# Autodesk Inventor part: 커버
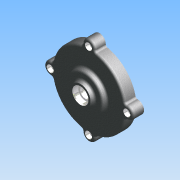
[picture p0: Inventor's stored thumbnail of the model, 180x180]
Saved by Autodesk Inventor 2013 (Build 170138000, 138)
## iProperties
Company: 한국ATC센터
Created: 2014-07
Part Number: 커버
Document SubType Name: 모델링
Designer: KYOUNG IL JANG
Material: 알루미늄 6061
Mass: 196.659 g
Surface Area: 278.607 cm^2
Volume: 72.5678 cm^3
Density: 2.71 g/cm^3
변환 표준: STEP AP214IS
파일 이름: C:\Users\SeoGD\Desktop\?쒗뿕\而ㅻ쾭-1.stp
전처리기: Build: 253, Release: 2010 SP1 - Date: Wed 07/29/2009
전송 단위: 밀리미터
불확실성: 0.01
Author: KYOUNG IL JANG
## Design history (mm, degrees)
sketch "스케치1"
  geometry: L1 (0, 0)-(0, 26); L2 (50, 0)-(50, 15); L3 (50, 15)-(25, 15); L4 (25, 15)-(25, 21); L5 (25, 21)-(15, 21); L6 (15, 21)-(13.66, 26); L7 (13.66, 26)-(10, 26); L8 (50, 0)-(45, 0); L9 (45, 0)-(45, 10); L10 (45, 10)-(14.5, 10); L11 (14.5, 10)-(13.266, 3); L12 (13.266, 3)-(11, 3); L13 (11, 3)-(11, 16); L14 (11, 16)-(7.5, 16); L15 (7.5, 16)-(7.5, 19); L16 (7.5, 19)-(10, 19); L17 (10, 19)-(10, 26)
  constraints: 34 end point, 10 parallel, 2 perpendicular, 2 point on line, 1 vertical
  dimensions: "d11" = 100 diameter of L2 L1; "d12" = 22 diameter of L13 L1; "d13" = 90 diameter of L9 L1; "d14" = 15 distance between parallel lines of L3 L8; "d15" = 10 distance between parallel lines of L8 L10; "d16" = 29 diameter of L10.end L1; "d17" = 100 deg angle of L11 L10; "d18" = 7 distance between parallel lines of L12 L10; "d19" = 13 distance between parallel lines of L14 L12; "d20" = 3 distance between parallel lines of L16 L14; "d21" = 15 diameter of L15 L1; "d22" = 20 diameter of L17 L1; "d23" = 30 diameter of L5.end L1; "d24" = 6 distance between parallel lines of L5 L3; "d25" = 50 diameter of L4 L1; "d26" = 105 deg angle of L5 L6; "d50" = 26 distance of L1.start L1.end
revolve "회전1" sketch "스케치1" stored, may be unused: angle "d27" = 90 deg
sketch "스케치2" dims "d29" = 104
  geometry: A1 r 8.5 centre (0, 52) between (8.074, 49.344) and (-8.074, 49.344); A2 r 50 centre (0, 0) between (-8.074, 49.344) and (8.074, 49.344) reference; 2 further points
  constraints: 4 point on circle, 2 vertical alignment, 1 centre point, 1 coincident, 2 other
  dimensions: "d28" = 17 diameter of A1
extrude "돌출1" join sketch "스케치2" stored distance "d30" = 10; taper "d31" = 0 deg
fillet "모깎기3" dims "d32" = 3
fillet "모깎기4" dims "d45" = 3, "d46" = 0.2
chamfer "모따기1" distance "d47" = 1; stored, may be unused: second distance "d48" = 2, angle "d49" = 45 deg
hole "구멍2" diameter "d38" = 5.5; stored, may be unused: countersink angle "d42" = 90 deg, drill point angle "d44" = 118 deg; dims "d36" = 10, "d37" = 10, "d39" = 6, "d40" = 9.5, "d41" = 5.4, "d43" = 8
node "솔리드1"
node "솔리드 본체"
node "곡면 본체"
pattern_circular "원형 패턴1" dims angle "d34" = 360 deg
pattern_circular "원형 패턴2" dims angle "d52" = 360 deg
node "솔리드2"
